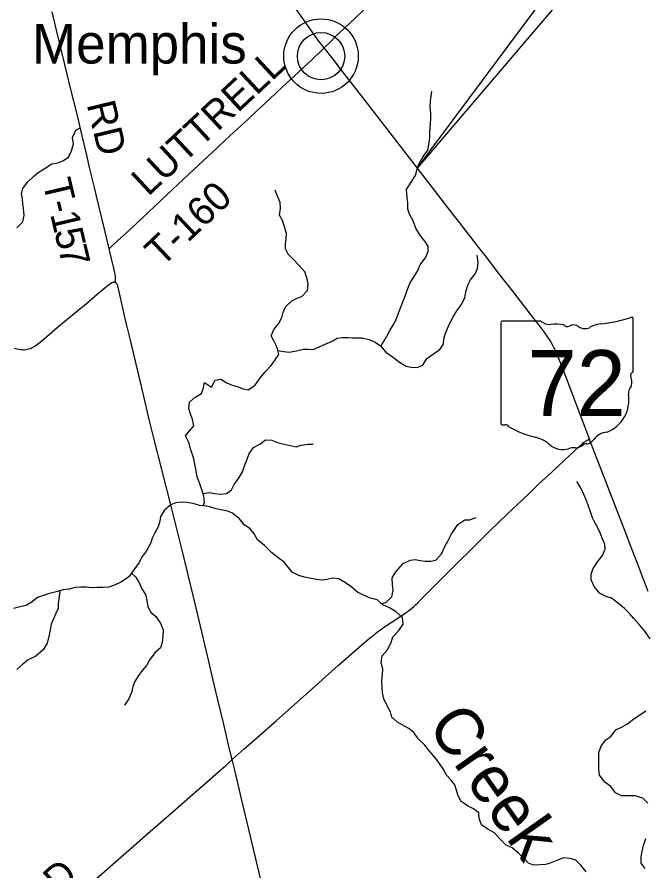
# Model space of a CAD drawing. Extents: x 0 to 34, y 0 to 22.
# Drawn here: x 4.871 to 6.121, y 16.393 to 18.098 of the extents above; entities that cross this region are included whole.
import ezdxf

# ---------------------------------------------------------------- set-up
doc = ezdxf.new("R2010")
doc.units = 0
for name, color, linetype in [('GM_X_County_Road', 7, 'Continuous'), ('GM_X_Minor_River', 7, 'Continuous'), ('GM_X_Minor_River_Text', 7, 'Continuous'), ('GM_X_State_Location', 7, 'Continuous'), ('GM_X_State_Route', 7, 'Continuous'), ('GM_X_State_Shield', 7, 'Continuous'), ('GM_X_Township_Road', 7, 'Continuous'), ('GM_X_Township_Road_Text', 7, 'Continuous'), ('GM_X_Unincorporated', 7, 'Continuous'), ('GM_X_Unincorporated_Location', 7, 'Continuous'), ('GM_X_Unincorporated_Text', 7, 'Continuous'), ('SH_Text', 7, 'Continuous')]:
    doc.layers.add(name, color=color, linetype=linetype)

msp = doc.modelspace()

# ---------------------------------------------------------------- linework, layer by layer
at = {"layer": 'GM_X_County_Road'}
for points in [[(5.0668, 17.5675), (5.0658, 17.5679), (5.0644, 17.5682), (5.063, 17.5681), (5.0616, 17.5678), (5.0598, 17.567), (5.0571, 17.5652), (5.053, 17.5622), (5.0305, 17.5435), (5.0092, 17.5254), (4.9887, 17.5083), (4.9509, 17.477), (4.919, 17.4502), (4.9113, 17.444), (4.9068, 17.4408), (4.9005, 17.437), (4.8988, 17.4361), (4.8971, 17.4352), (4.8943, 17.4343), (4.891, 17.4336), (4.888, 17.4331), (4.8854, 17.4329), (4.8837, 17.4329), (4.8807, 17.433), (4.8776, 17.4332), (4.8734, 17.4339), (4.8656, 17.4358)], [(5.2998, 16.6151), (5.2946, 16.6361), (5.2822, 16.6887), (5.2712, 16.7346), (5.264, 16.7649), (5.2483, 16.8307), (5.2237, 16.9347), (5.2112, 16.9867), (5.1998, 17.0332), (5.1893, 17.076), (5.1797, 17.1158), (5.1596, 17.194), (5.1428, 17.2596), (5.1344, 17.294), (5.1226, 17.3435), (5.0968, 17.4523), (5.0886, 17.4874), (5.073, 17.5553), (5.0715, 17.5609), (5.071, 17.5623), (5.0705, 17.5633), (5.0701, 17.5642), (5.0696, 17.565), (5.069, 17.566), (5.068, 17.5669), (5.0668, 17.5675)], [(5.4736, 15.8768), (5.4668, 15.9062), (5.4525, 15.9699), (5.4338, 16.0503), (5.4262, 16.083), (5.4012, 16.1901), (5.3909, 16.2337), (5.3826, 16.2687), (5.3726, 16.3104), (5.3665, 16.3358), (5.3539, 16.389), (5.3368, 16.459), (5.3183, 16.537), (5.305, 16.5939), (5.2998, 16.6151)]]:
    msp.add_lwpolyline(points, dxfattribs=at)
at = {"layer": 'GM_X_Minor_River'}
for points in [[(5.5963, 17.4404), (5.6029, 17.451), (5.6087, 17.4608), (5.6145, 17.4717), (5.6233, 17.4861), (5.6276, 17.4959), (5.6338, 17.5115), (5.6384, 17.524), (5.6462, 17.5444), (5.6505, 17.5554), (5.654, 17.566), (5.6605, 17.5758), (5.6693, 17.5905), (5.6759, 17.6042), (5.6855, 17.617), (5.6909, 17.6299), (5.691, 17.6401), (5.6843, 17.6504), (5.6745, 17.663), (5.6662, 17.6764), (5.6607, 17.6908), (5.6539, 17.7042), (5.6506, 17.7141), (5.6503, 17.7266), (5.6489, 17.7368), (5.6475, 17.7536), (5.6571, 17.7683), (5.6656, 17.7811), (5.6687, 17.794), (5.6722, 17.8039), (5.6807, 17.819), (5.6903, 17.8318), (5.6927, 17.8462), (5.6943, 17.8576), (5.694, 17.8686), (5.6953, 17.8853), (5.6965, 17.8952), (5.6962, 17.9058), (5.6948, 17.918), (5.6952, 17.9301), (5.6968, 17.94), (5.698, 17.9498)], [(4.8699, 17.677), (4.8822, 17.689), (4.8846, 17.7019), (4.8831, 17.7152), (4.8821, 17.7247), (4.8814, 17.7346), (4.8796, 17.7448), (4.8819, 17.7551), (4.8912, 17.7679), (4.9034, 17.7792), (4.913, 17.7871), (4.9267, 17.7957), (4.9397, 17.8048), (4.9519, 17.8069), (4.9618, 17.8107), (4.9732, 17.8178), (4.9794, 17.8303), (4.9833, 17.8447), (4.9815, 17.8572), (4.9877, 17.8716), (4.9968, 17.8763)], [(5.2417, 17.122), (5.2445, 17.1283), (5.2435, 17.1412), (5.239, 17.1534), (5.2353, 17.1656), (5.2301, 17.1793), (5.2279, 17.1914), (5.2261, 17.2017), (5.2236, 17.2154), (5.2198, 17.2256), (5.2165, 17.2355), (5.2136, 17.2485), (5.2068, 17.2618), (5.2145, 17.2716), (5.2233, 17.2814), (5.2208, 17.2947), (5.2167, 17.3046), (5.213, 17.3161), (5.2146, 17.3289), (5.2257, 17.3384), (5.2383, 17.3459), (5.2429, 17.3572), (5.2449, 17.3678), (5.2585, 17.359), (5.2658, 17.3726), (5.2769, 17.3744), (5.289, 17.3675), (5.2999, 17.3629), (5.3098, 17.3601), (5.3215, 17.3551), (5.3314, 17.3535), (5.3451, 17.3618), (5.3543, 17.3754), (5.3655, 17.3893), (5.3773, 17.4021), (5.3858, 17.4131), (5.3927, 17.424), (5.3898, 17.4377), (5.3827, 17.4511), (5.3778, 17.461), (5.3828, 17.4738), (5.3924, 17.4852), (5.3986, 17.498), (5.4013, 17.5083), (5.4068, 17.52), (5.419, 17.5309), (5.4293, 17.5361), (5.4388, 17.5395), (5.4499, 17.5515), (5.4512, 17.5644), (5.4497, 17.5751), (5.4445, 17.5888), (5.4332, 17.6014), (5.4212, 17.614), (5.4118, 17.6243), (5.4065, 17.6346), (5.4062, 17.6441), (5.4075, 17.6544), (5.4079, 17.6657), (5.4039, 17.6787), (5.4002, 17.6916), (5.3942, 17.7023), (5.3962, 17.7156), (5.3955, 17.7273), (5.3903, 17.7399), (5.3855, 17.7521)], [(5.3911, 17.4317), (5.4026, 17.43), (5.4136, 17.4288), (5.4281, 17.4314), (5.4421, 17.4347), (5.4516, 17.4346), (5.4615, 17.4342), (5.4718, 17.4383), (5.487, 17.445), (5.4996, 17.4506), (5.5095, 17.4562), (5.5202, 17.4576), (5.5304, 17.4579), (5.5399, 17.4571), (5.5498, 17.4574), (5.5593, 17.4573), (5.5729, 17.4538), (5.5854, 17.4484), (5.5956, 17.4411), (5.6065, 17.4289), (5.6216, 17.4178), (5.6318, 17.4101), (5.6469, 17.4009), (5.6568, 17.3985), (5.6686, 17.3981), (5.68, 17.4029), (5.6885, 17.4158), (5.7014, 17.4252), (5.7144, 17.4342), (5.7213, 17.4444), (5.7222, 17.4542), (5.7245, 17.4645), (5.7296, 17.4758), (5.7338, 17.4864), (5.74, 17.4981), (5.7481, 17.511), (5.7569, 17.5231), (5.7639, 17.5371), (5.7662, 17.5492), (5.7698, 17.5625), (5.7755, 17.5727), (5.7844, 17.5847), (5.7894, 17.5953), (5.7906, 17.6075), (5.7885, 17.6223)], [(5.2416, 17.1462), (5.2538, 17.1483), (5.2652, 17.1467), (5.2769, 17.1451), (5.2887, 17.1462), (5.2983, 17.1537), (5.304, 17.1643), (5.3136, 17.1786), (5.3206, 17.1896), (5.3241, 17.2013), (5.3291, 17.2127), (5.3338, 17.2263), (5.3426, 17.238), (5.3552, 17.2451), (5.3666, 17.2538), (5.3792, 17.2526), (5.392, 17.2475), (5.4034, 17.2448), (5.4152, 17.242), (5.4277, 17.2397), (5.4376, 17.243), (5.4513, 17.2448), (5.4615, 17.2451)], [(6.134, 16.8559), (6.1212, 16.8743), (6.1122, 16.885), (6.1012, 16.8968), (6.0926, 16.9067), (6.0828, 16.9167), (6.0681, 16.9289), (6.0568, 16.9374), (6.0458, 16.9409), (6.0325, 16.9474), (6.022, 16.9604), (6.0164, 16.9741), (6.0158, 16.9851), (6.02, 16.9969), (6.0289, 17.0097), (6.0388, 17.0229), (6.0443, 17.035), (6.0432, 17.0449), (6.038, 17.0575), (6.0339, 17.0681), (6.0294, 17.0777), (6.0238, 17.0872), (6.0186, 17.0975), (6.0145, 17.1097), (6.0104, 17.1233), (6.0059, 17.134), (6.0018, 17.1447), (5.9955, 17.1576), (5.9872, 17.1702)], [(5.6521, 16.6773), (5.6393, 16.6842), (5.6295, 16.6896), (5.6181, 16.6996), (5.616, 16.7106), (5.6085, 16.7239), (5.6021, 16.7365), (5.5999, 16.7487), (5.5989, 16.7589), (5.5986, 16.7718), (5.5999, 16.7855), (5.6003, 16.7954), (5.5974, 16.8083), (5.599, 16.8223), (5.6093, 16.8333), (5.6171, 16.8488), (5.6202, 16.8605), (5.6321, 16.873), (5.6413, 16.8858), (5.6399, 16.8987), (5.6267, 16.9102), (5.6138, 16.9183), (5.6006, 16.9244), (5.5893, 16.934), (5.576, 16.9375), (5.562, 16.9433), (5.5499, 16.9491), (5.5363, 16.9606), (5.5261, 16.9683), (5.5129, 16.9763), (5.5, 16.9776), (5.4886, 16.9746), (5.4791, 16.9736), (5.4685, 16.9748), (5.4571, 16.9768), (5.4442, 16.9791), (5.4328, 16.9826), (5.4196, 16.9892), (5.4113, 16.9995), (5.4034, 17.009), (5.3906, 17.0186), (5.3781, 17.0286), (5.3642, 17.0427), (5.3506, 17.0538), (5.3435, 17.066), (5.3349, 17.0767), (5.3239, 17.084), (5.3145, 17.0959), (5.3005, 17.1074), (5.2903, 17.1112), (5.2808, 17.1128), (5.2679, 17.1156), (5.2551, 17.1195), (5.2441, 17.1218), (5.2346, 17.1227), (5.2221, 17.1262), (5.2092, 17.1285), (5.1974, 17.1294), (5.1872, 17.1276), (5.1773, 17.1235), (5.165, 17.1133), (5.1569, 17.1008), (5.1557, 17.0914), (5.1522, 17.08), (5.1449, 17.0668), (5.1399, 17.0569), (5.1371, 17.0467), (5.1291, 17.032), (5.1191, 17.0187), (5.1141, 17.0085), (5.1033, 16.9938), (5.0937, 16.9802), (5.0788, 16.9701), (5.0662, 16.9641), (5.0537, 16.9593), (5.0419, 16.9586), (5.0301, 16.9587), (5.0187, 16.958), (5.0088, 16.9592), (4.9975, 16.9597), (4.9864, 16.9586), (4.9746, 16.9557), (4.9625, 16.9539), (4.9511, 16.9505), (4.9351, 16.9465), (4.9233, 16.9428), (4.9111, 16.9387), (4.8985, 16.9289), (4.8889, 16.9229), (4.8737, 16.9192), (4.8634, 16.917)], [(5.5981, 16.9265), (5.6067, 16.9289), (5.6182, 16.9399), (5.6209, 16.9531), (5.6195, 16.9642), (5.6189, 16.9782), (5.6266, 16.9903), (5.6411, 17.0065), (5.6552, 17.0132), (5.6651, 17.0147), (5.675, 17.0127), (5.6848, 17.0111), (5.6962, 17.0114), (5.7061, 17.0136), (5.7176, 17.0257), (5.7246, 17.0416), (5.7303, 17.0514), (5.7365, 17.0646), (5.7434, 17.0745), (5.75, 17.0847), (5.7641, 17.0937), (5.7736, 17.094), (5.7865, 17.0984)], [(5.0989, 16.9876), (5.1077, 16.9794), (5.1149, 16.9668), (5.1186, 16.9573), (5.1272, 16.9431), (5.1298, 16.9329), (5.1312, 16.9203), (5.1372, 16.9097), (5.1474, 16.9009), (5.1575, 16.886), (5.1623, 16.8742), (5.1615, 16.8617), (5.1602, 16.8488), (5.1567, 16.8385), (5.146, 16.8287), (5.1353, 16.8152), (5.1291, 16.8031), (5.1203, 16.7932), (5.1115, 16.7812), (5.1053, 16.7713), (5.1014, 16.7611), (5.0987, 16.7494), (5.0933, 16.7361), (5.0852, 16.724)], [(4.9557, 16.9519), (4.9548, 16.9403), (4.9528, 16.9266), (4.9523, 16.9171), (4.9473, 16.9058), (4.9388, 16.8853), (4.9368, 16.8743), (4.9348, 16.8641), (4.9305, 16.8478), (4.9224, 16.8342), (4.9079, 16.8214), (4.893, 16.8143), (4.8819, 16.8057), (4.8704, 16.7947)], [(6.129, 16.528), (6.1193, 16.5379), (6.1037, 16.5426), (6.0764, 16.5428), (6.065, 16.549), (6.0553, 16.5612), (6.0432, 16.57), (6.033, 16.5837), (6.0312, 16.5963), (6.0317, 16.6088), (6.0314, 16.6183), (6.0315, 16.6293), (6.0362, 16.6422), (6.045, 16.6539), (6.0557, 16.6618), (6.0653, 16.6746), (6.079, 16.681), (6.0885, 16.6866), (6.1012, 16.6967), (6.1126, 16.7039), (6.1252, 16.7125)], [(6.006, 16.3907), (5.9955, 16.4041), (5.9853, 16.414), (5.974, 16.4175), (5.9611, 16.4188), (5.9344, 16.4083), (5.9249, 16.4054), (5.9139, 16.4047), (5.901, 16.4044), (5.8911, 16.4083), (5.8825, 16.4178), (5.8708, 16.4285), (5.8583, 16.4389), (5.8466, 16.4443), (5.8338, 16.4569), (5.8229, 16.4688), (5.81, 16.4765), (5.7972, 16.4849), (5.7927, 16.4978), (5.7917, 16.5085), (5.7811, 16.5169), (5.7694, 16.5227), (5.7558, 16.5319), (5.7498, 16.5449), (5.7472, 16.5544), (5.7443, 16.565), (5.7364, 16.5749), (5.727, 16.5849), (5.7221, 16.5944), (5.7146, 16.6051), (5.7064, 16.6173), (5.6939, 16.6314), (5.6845, 16.644), (5.671, 16.6563), (5.6623, 16.6693), (5.6521, 16.6773)], [(6.1238, 16.3974), (6.1156, 16.4085), (6.116, 16.4207), (6.118, 16.4316), (6.1204, 16.4438), (6.1251, 16.4578)]]:
    msp.add_lwpolyline(points, dxfattribs=at)
at = {"layer": 'GM_X_State_Route'}
msp.add_lwpolyline([(6.1301, 16.951), (6.1201, 16.9764), (6.1077, 17.0089), (6.0939, 17.0442), (6.0865, 17.064), (6.0791, 17.0825), (6.05, 17.1584), (6.0282, 17.2151), (6.0144, 17.2506), (6.0125, 17.2554), (5.9975, 17.2953), (5.9766, 17.3499), (5.9673, 17.3749), (5.9566, 17.4028), (5.9536, 17.4103), (5.9508, 17.4173), (5.9485, 17.423), (5.9461, 17.4285), (5.9441, 17.4333), (5.9419, 17.4376), (5.9396, 17.4422), (5.9369, 17.4469), (5.9347, 17.4509), (5.9323, 17.4547), (5.9297, 17.4588), (5.9226, 17.469), (5.9126, 17.4825), (5.8973, 17.5021), (5.884, 17.5193), (5.8598, 17.5501), (5.8292, 17.5892), (5.8076, 17.6173), (5.7893, 17.6409), (5.7511, 17.6899), (5.7406, 17.7037), (5.719, 17.7318), (5.6873, 17.7725), (5.6535, 17.8163), (5.6377, 17.837), (5.6085, 17.8749), (5.5649, 17.9308), (5.5437, 17.9583), (5.52, 17.9887), (5.5012, 18.0134), (5.4835, 18.0361), (5.4809, 18.0394), (5.473, 18.0498), (5.4594, 18.0683), (5.4426, 18.0921), (5.3875, 18.1696)], dxfattribs=at)
at = {"layer": 'GM_X_State_Shield'}
for p, q in [((6.0997, 17.3906), (6.0997, 17.4953)), ((5.8361, 17.4868), (5.8361, 17.2867)), ((5.9159, 17.4903), (5.8387, 17.4903)), ((6.0997, 17.3906), (6.0997, 17.3906))]:
    msp.add_line(p, q, dxfattribs=at)
for centre, radius, start, end in [((6.0058, 17.7631), 0.2796, 275.8445, 288.9065), ((6.0968, 17.4957), 0.00294, 351.8621, 97.738), ((5.8391, 17.4873), 0.00305, 98.1301, 188.1301), ((5.9343, 17.5135), 0.0296, 231.6195, 271.1119), ((5.9441, 17.3779), 0.1064, 80.4867, 94.9883), ((5.9682, 17.4883), 0.00855, 219.7921, 297.1024), ((5.9808, 17.4652), 0.0178, 54.4667, 119.1411), ((6.0037, 17.4969), 0.0214, 233.8562, 294.8282), ((6.0415, 17.4292), 0.0563, 97.3462, 120.7689), ((6.0966, 17.3902), 0.00314, 289.6038, 7.7341), ((6.0991, 17.3829), 0.00454, 107.944, 210.337), ((6.0702, 17.3696), 0.0273, 340.033, 23.6496), ((6.1103, 17.3468), 0.0198, 136.8065, 186.9296), ((6.0215, 17.3334), 0.0699, 292.3089, 8.9858), ((5.8391, 17.2863), 0.00308, 171.9584, 258.3066), ((5.8396, 17.3068), 0.0235, 267.339, 280.6039), ((5.8444, 17.2752), 0.00848, 29.7484, 93.2717), ((5.9515, 17.455), 0.2019, 240.4129, 257.1985), ((5.8913, 17.1968), 0.0632, 47.1842, 75.836), ((6.0024, 17.2673), 0.0226, 282.8732, 323.2771), ((6.051, 17.2305), 0.0383, 94.4031, 142.5768), ((5.9596, 17.2742), 0.0401, 230.7004, 286.2918), ((5.9827, 17.205), 0.0329, 85.6951, 111.2099), ((5.9857, 17.2592), 0.0214, 268.777, 315.5493), ((6.005, 17.2398), 0.00601, 65.7517, 132.6484)]:
    msp.add_arc(centre, radius, start, end, dxfattribs=at)
at = {"layer": 'GM_X_Township_Road'}
for points in [[(5.4835, 18.0361), (5.4951, 18.0472), (5.5055, 18.0579), (5.5234, 18.0751), (5.582, 18.1299), (5.6057, 18.1518), (5.6276, 18.172), (5.6664, 18.2087), (5.7125, 18.2523), (5.7503, 18.2874), (5.7819, 18.3173), (5.8228, 18.3554), (5.8901, 18.4181), (5.9581, 18.4809), (5.9796, 18.5007), (6.0181, 18.5359), (6.0287, 18.5455), (6.0638, 18.5772), (6.1316, 18.6392), (6.1545, 18.6602), (6.2166, 18.7166), (6.2556, 18.7523), (6.2913, 18.7845)], [(5.0541, 17.6349), (5.0463, 17.6686), (5.0337, 17.7206), (5.0251, 17.7575), (5.016, 17.7949), (5.0097, 17.8221), (5.0005, 17.8602), (4.9903, 17.9037), (4.9781, 17.9532), (4.9662, 18.0027), (4.9493, 18.0715), (4.9405, 18.1084)], [(5.0541, 17.6349), (5.0613, 17.6415), (5.0713, 17.6508), (5.0895, 17.6678), (5.1199, 17.6963), (5.1581, 17.7318), (5.1919, 17.7639), (5.2227, 17.7928), (5.2432, 17.8118), (5.259, 17.8267), (5.284, 17.85), (5.2952, 17.8607), (5.3314, 17.8939), (5.3489, 17.9107), (5.3575, 17.9187), (5.3737, 17.9332), (5.3892, 17.9476), (5.4063, 17.9639), (5.4413, 17.9965), (5.46, 18.0138), (5.479, 18.0317), (5.4835, 18.0361)], [(5.0668, 17.5675), (5.0669, 17.5695), (5.067, 17.5712), (5.0671, 17.5724), (5.0672, 17.5741), (5.0671, 17.5756), (5.067, 17.5775), (5.067, 17.5791), (5.0668, 17.5806), (5.0664, 17.5831), (5.0634, 17.5961), (5.0547, 17.6323), (5.0541, 17.6349)], [(5.2998, 16.6151), (5.3237, 16.6366), (5.349, 16.6587), (5.3881, 16.6933), (5.4592, 16.7564), (5.4923, 16.7855), (5.5122, 16.8034), (5.5325, 16.8216), (5.5639, 16.849), (5.5724, 16.8561), (5.5777, 16.8605), (5.5811, 16.8632), (5.5857, 16.8667), (5.59, 16.8701), (5.596, 16.8744), (5.6025, 16.8792), (5.6078, 16.8828), (5.6169, 16.889), (5.6362, 16.9015), (5.647, 16.9088), (5.6509, 16.9116), (5.6545, 16.9144), (5.6581, 16.9174), (5.6621, 16.9208), (5.6657, 16.9241), (5.6702, 16.9284), (5.6763, 16.9347), (5.6844, 16.943), (5.691, 16.9497), (5.7125, 16.9713), (5.755, 17.0131), (5.7705, 17.0284), (5.7867, 17.0446), (5.8142, 17.0716), (5.8494, 17.1058), (5.8791, 17.134), (5.8948, 17.1491), (5.9133, 17.1667), (5.936, 17.1878), (5.9637, 17.2137), (5.9914, 17.2396), (5.9993, 17.2465), (6.0011, 17.2479), (6.0033, 17.2495), (6.0049, 17.2506), (6.0064, 17.2515), (6.0125, 17.2554)], [(4.828, 16.202), (4.8986, 16.2638), (4.9202, 16.2825), (4.9538, 16.312), (4.9834, 16.3377), (4.9896, 16.3432), (4.9945, 16.3476), (4.9998, 16.3522), (5.0076, 16.359), (5.0133, 16.364), (5.0937, 16.4343), (5.1264, 16.4629), (5.1929, 16.5209), (5.2208, 16.5457), (5.2452, 16.5669), (5.2722, 16.5908), (5.2877, 16.6042), (5.2998, 16.6151)]]:
    msp.add_lwpolyline(points, dxfattribs=at)
at = {"layer": 'GM_X_Unincorporated'}
for radius in [0.0744, 0.0472]:
    msp.add_circle((5.4771, 18.0196), radius, dxfattribs=at)
at = {"layer": 'GM_X_Unincorporated_Location'}
msp.add_line((5.4771, 18.0196), (5.4771, 18.0196), dxfattribs=at)
at = {"layer": 'SH_Text'}
msp.add_lwpolyline([(6.2913, 19.0362), (7.4233, 19.0362), (7.4233, 18.7733), (6.5017, 18.7733), (5.6692, 17.796), (6.3965, 18.7733), (6.2913, 18.7733)], close=True, dxfattribs=at)

# ---------------------------------------------------------------- texts
at = {"layer": 'GM_X_Minor_River_Text'}
msp.add_text('Creek', height=0.09469, rotation=305.1645, dxfattribs=at).set_placement((5.6871, 16.6829))
at = {"layer": 'GM_X_State_Location'}
for s in ['s', 'r']:
    msp.add_text(s, height=0.000189, dxfattribs=at).set_placement((5.9649, 17.3735))
msp.add_text('72', height=0.000189, rotation=0, dxfattribs=at).set_placement((5.9172, 17.3597))
at = {"layer": 'GM_X_State_Shield'}
msp.add_text('72', height=0.13184, dxfattribs=at).set_placement((5.8892, 17.3008))
at = {"layer": 'GM_X_Township_Road_Text'}
for s, height, rotation, p in [('LUTTRELL', 0.05682, 43.0185, (5.1319, 17.7382)), ('RD', 0.05682, 283.4476, (5.0092, 17.9236)), ('T', 0.0568, 283.24, (4.9212, 17.7685)), ('T-160', 0.05682, 43.4107, (5.1591, 17.5968)), ('-', 0.0568, 283.25, (4.931, 17.7271)), ('1', 0.0568, 283.2579, (4.9363, 17.7044)), ('5', 0.0568, 283.3153, (4.9444, 17.6703)), ('7', 0.0568, 283.7041, (4.9525, 17.6358)), ('RD', 0.05682, 41.9127, (4.9139, 16.306))]:
    msp.add_text(s, height=height, rotation=rotation, dxfattribs=at).set_placement(p)
at = {"layer": 'GM_X_Unincorporated_Text'}
msp.add_text('Memphis', height=0.07898, rotation=0, dxfattribs=at).set_placement((4.9005, 18.0049))

doc.saveas('drawing.dxf')
